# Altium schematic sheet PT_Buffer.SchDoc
size A4
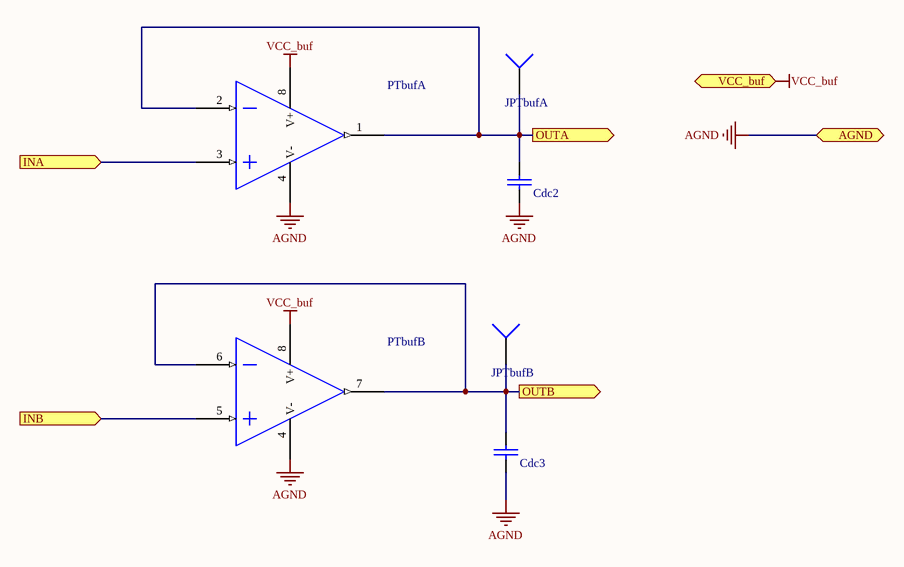
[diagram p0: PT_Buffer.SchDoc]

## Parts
Cdc2  47nF  [ECE-CAPC2012-0805SM]  (value not drawn)
Cdc3  47nF  [ECE-CAPC2012-0805SM]  (value not drawn)
JPTbufA  TEST PIN  [ECE-HDR1TH]  (value not drawn)
JPTbufB  TEST PIN  [ECE-HDR1TH]  (value not drawn)
PTbuf  LT6221  [ECE-SO8]  (value not drawn)  (parts A,B of 2)

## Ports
AGND, INA (in), INB (in), OUTA (out), OUTB (out), VCC_buf (in)

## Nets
AGND: Cdc2.2 Cdc3.2 PTbuf.4(V-) ; port AGND
VCC_buf: PTbuf.8(V+) ; port VCC_buf
INA: PTbuf.3(IN1(+)) ; port INA
INB: PTbuf.5(IN2(+)) ; port INB
OUTA: Cdc2.1 JPTbufA.1 PTbuf.1(OUT1) PTbuf.2(IN1(-)) ; port OUTA
OUTB: Cdc3.1 JPTbufB.1 PTbuf.6(IN2(-)) PTbuf.7(OUT2) ; port OUTB

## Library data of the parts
Cdc2 Cdc3 = CAP000522: CAP CER 47nF 50V X7R SM0805; Manufactuer: Samsung; Manufacturer-PN: CL21B473KBCNNNC; Assembly Method: Surface Mount; Item Type: Item; Path: ece/ts/Lists/Stock Inventory
JPTbufA JPTbufB = CON000017: Value: 1 way; Assembly Method: Through hole; Item Type: Item; Path: ece/ts/Lists/Stock Inventory
PTbuf = OPA000102: IC OPAMP LT6221 DUAL SM; Manufactuer: Linear Technology; Manufacturer-PN: LT6221CS8#TRPBF; Assembly Method: Surface Mount; Item Type: Item; Path: ece/ts/Lists/Stock Inventory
